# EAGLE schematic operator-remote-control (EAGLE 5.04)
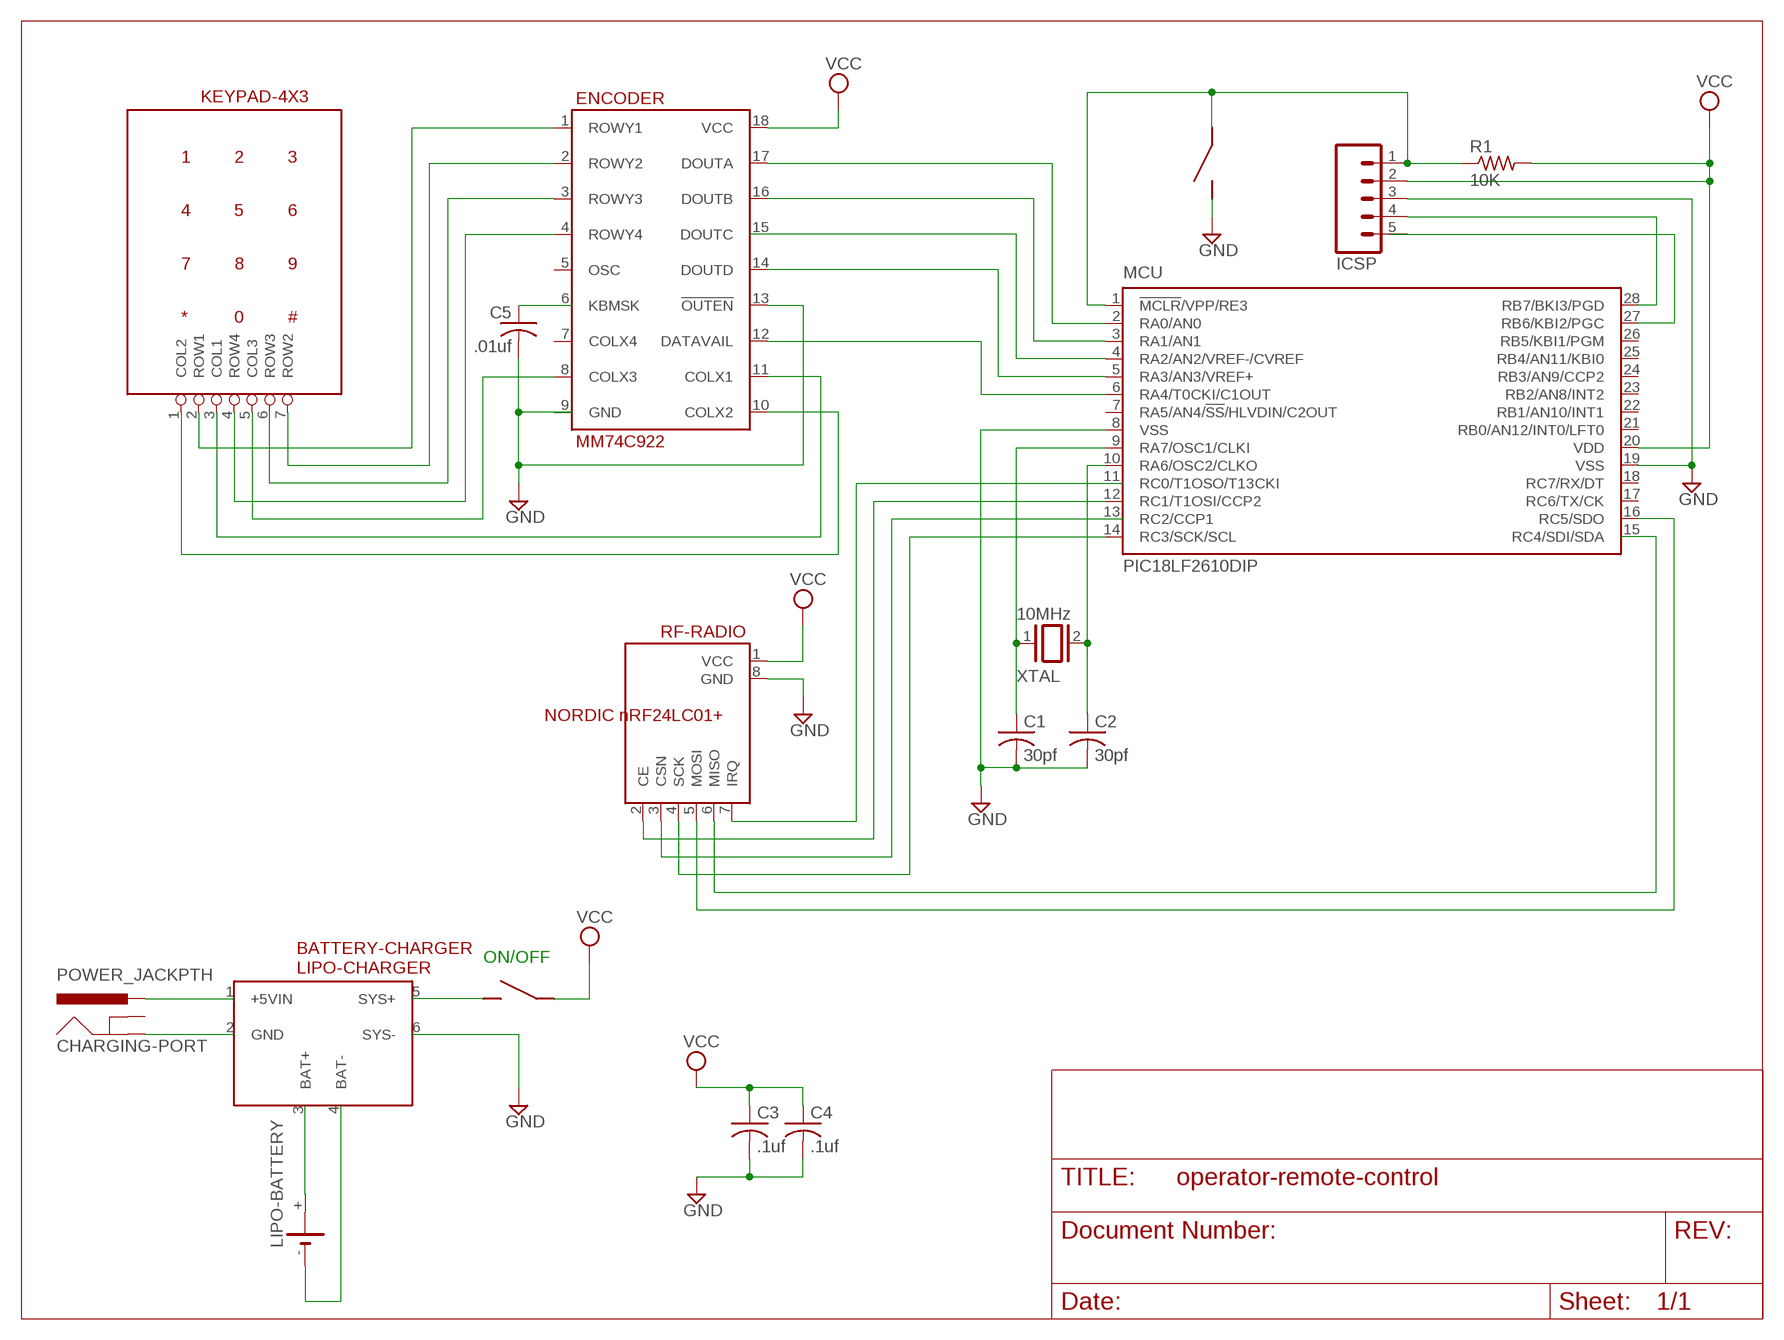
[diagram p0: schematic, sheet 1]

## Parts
BATTERY-CHARGER  LIPO-CHARGER  [8SIL]
C1  30pf  C-US102-043X133  [C102-043X133]
C2  30pf  C-US102-043X133  [C102-043X133]
C3  .1uf  C-US102-043X133  [C102-043X133]
C4  .1uf  C-US102-043X133  [C102-043X133]
C5  .01uf  C-US102-043X133  [C102-043X133]
CHARGING-PORT  POWER_JACKPTH  [POWER_JACK_PTH]
ENCODER  MM74C922  [18DIL]
ICSP  M05  [05P]
KEYPAD-4X3  KEYPAD43  [4X3]
LIPO-BATTERY  CR2430V  [CR2430V]
MCU  PIC18LF2610DIP  [DIL28-3]
ON-OFF  PUSH-BUTTON-SWITCH  [2SIL]
R1  10K  R-US_0617/22  [0617/22]
RESET  PUSH-BUTTON-SWITCH  [2SIL]
RF-RADIO  NORDIC nRF24LC01+  NORDIC-BREAKOUT  [8SIL]
XTAL  10MHz  XTAL  [Q]

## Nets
BBB: RF-RADIO.7(IRQ)
GND: BATTERY-CHARGER.6(SYS-) C1.2 C2.2 C3.2 C4.2 C5.2 ENCODER.9(GND) ENCODER.13(!OUTEN) ICSP.3 MCU.8(VSS) MCU.19(VSS) RESET.NO RF-RADIO.8(GND)
N$1: ENCODER.10(COLX2) KEYPAD-4X3.1(COL2)
N$2: ENCODER.1(ROWY1) KEYPAD-4X3.2(ROW1)
N$3: ENCODER.11(COLX1) KEYPAD-4X3.3(COL1)
N$4: ENCODER.8(COLX3) KEYPAD-4X3.5(COL3)
N$5: ENCODER.4(ROWY4) KEYPAD-4X3.4(ROW4)
N$6: ENCODER.3(ROWY3) KEYPAD-4X3.6(ROW3)
N$7: ENCODER.2(ROWY2) KEYPAD-4X3.7(ROW2)
N$8: ENCODER.12(DATAVAIL) MCU.6(RA4/T0CKI/C1OUT)
N$9: C1.1 MCU.9(RA7/OSC1/CLKI) XTAL.1
N$10: C2.1 MCU.10(RA6/OSC2/CLKO) XTAL.2
N$11: ENCODER.14(DOUTD) MCU.5(RA3/AN3/VREF+)
N$12: ENCODER.15(DOUTC) MCU.4(RA2/AN2/VREF-/CVREF)
N$13: ENCODER.16(DOUTB) MCU.3(RA1/AN1)
N$14: ENCODER.17(DOUTA) MCU.2(RA0/AN0)
N$15: ICSP.1 MCU.1(!MCLR!/VPP/RE3) R1.1 RESET.COM
N$16: ICSP.4 MCU.28(RB7/BKI3/PGD)
N$17: MCU.27(RB6/KBI2/PGC)
N$18: BATTERY-CHARGER.1(+5VIN) CHARGING-PORT.PWR
N$19: C5.1
N$20: MCU.12(RC1/T1OSI/CCP2) RF-RADIO.2(CE)
N$21: RF-RADIO.3(CSN)
N$22: MCU.14(RC3/SCK/SCL) RF-RADIO.4(SCK)
N$23: MCU.16(RC5/SDO) RF-RADIO.5(MOSI)
N$24: RF-RADIO.6(MISO)
N$25: BATTERY-CHARGER.5(SYS+) ON-OFF.NO
N$26: BATTERY-CHARGER.2(GND) CHARGING-PORT.GND
N$27: BATTERY-CHARGER.3(BAT+) LIPO-BATTERY.+
N$28: BATTERY-CHARGER.4(BAT-) LIPO-BATTERY.-
VCC: C3.1 C4.1 ENCODER.18(VCC) ICSP.2 MCU.20(VDD) ON-OFF.COM R1.2 RF-RADIO.1(VCC)
Unconnected: CHARGING-PORT.GNDBREAK ENCODER.5(OSC) ENCODER.6(KBMSK) ENCODER.7(COLX4) ICSP.5 LIPO-BATTERY.+@1(+) MCU.7(RA5/AN4/!SS!/HLVDIN/C2OUT) MCU.11(RC0/T1OSO/T13CKI) MCU.13(RC2/CCP1) MCU.15(RC4/SDI/SDA) MCU.17(RC6/TX/CK) MCU.18(RC7/RX/DT) MCU.21(RB0/AN12/INT0/LFT0) MCU.22(RB1/AN10/INT1) MCU.23(RB2/AN8/INT2) MCU.24(RB3/AN9/CCP2) MCU.25(RB4/AN11/KBI0) MCU.26(RB5/KBI1/PGM)

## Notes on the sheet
- ON/OFF

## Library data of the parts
BATTERY-CHARGER = trl:LIPO-CHARGER
C1-C5 = rcl:C-US: CAPACITOR, American symbol
CHARGING-PORT = SparkFun:POWER_JACK: Power Jack This is the standard 5.5mm barrel jack for power. The PTH is the most common, proven, reliable, footprint. All others are experimental. The Slot footprint only works if the mill layer is transmitted to the PCB fab house so be warned. Spark Fun Electronics SKU : PRT-00119. Mating wall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
ENCODER = trl:MM74C922: 16-key encoder
ICSP = con-amp-quick:M05: AMP QUICK CONNECTOR
KEYPAD-4X3 = trl:KEYPAD43: 4x3 Keypad Input Device
LIPO-BATTERY = battery:CR2430V: LI BATTERY Varta
MCU = trl:PIC18LF2610: PIC18LF2610 28-Pin, No USB or EEPROM
ON-OFF RESET = trl:PUSH-BUTTON-SWITCH
R1 = resistor:R-US_: RESISTOR, American symbol
RF-RADIO = trl:NORDIC-BREAKOUT: Spark Fun Electronic's Nordic Semiconductor nRF24L01 with chip antenna
XTAL = special:XTAL: CRYSTAL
